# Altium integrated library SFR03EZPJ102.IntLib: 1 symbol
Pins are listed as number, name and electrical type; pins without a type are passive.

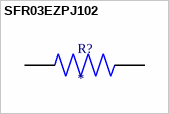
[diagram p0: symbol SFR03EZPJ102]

## SFR03EZPJ102
designator R?
MP: SFR03EZPJ102
footprint RESC1608X55N
pins: 1, 2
